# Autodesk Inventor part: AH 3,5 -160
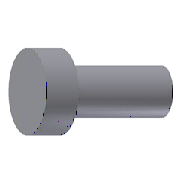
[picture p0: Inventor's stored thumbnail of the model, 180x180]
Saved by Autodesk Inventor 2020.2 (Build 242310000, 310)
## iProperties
Manager: www.cadconsulting.pl
Company: Fabian Stasiak CAD Consulting
Created: 2014-02
Part Number: AH 3,5 -160
Material: DIN 1.2210
Description: Ejector pins-hardened
Document SubType Name: Modeling
Standard: DIN 1530/ISO 6751
Designer: F.Stasiak
Standard Revision: 1
Manufacturer: DME
Language: pl-PL
Size Designation: 3,5 -160
Categories: <MemberInstance><Categories><Category DisplayName="Forma wtryskowa" InternalName="349578f2-f4d4-4954-8c09-8e99297a61c0" Mnemonic="MOLD"><Category DisplayName="K
Mass: 0.191827 g
Surface Area: 2.51725 cm^2
Volume: 0.191827 cm^3
Density: 7.85 g/cm^3
Appearance: Aluminium - ciemne
Catalog Web Link: www.expertbooks.pl
IsCustomPart: 1
Author: F.Stasiak
Subject: Zbiór ćwiczeń. Autodesk Inventor 2020. Kurs Professional
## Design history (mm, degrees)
sketch "Sketch1"
  geometry: L1 (0, 3.5)-(3, 3.5); L2 (0, 0)-(0, 3.5); L3 (3, 1.75)-(160, 1.75); L4 (160, 1.75)-(160, 0); L5 (0, 0)-(160, 0); L6 (3, 3.5)-(3, 1.75); 2 further points
  constraints: 12 end point, 4 point on line, 2 horizontal, 2 perpendicular, 1 coincident
  dimensions: "d6" = 3 distance of L1.start L1.end (derived); "d9" = 160 distance between parallel lines of L4 L2 (derived); "d10" = 7 diameter of L1 L5 (derived); "d13" = 3.5 diameter of L3 L5 (derived)
revolve "Revolution1" sketch "Sketch1" stored, may be unused: angle "d11" = 90 deg
fillet "Fillet1" dims "d29" = 0.3 (derived)
workplane "Work Plane1"
sketch "Sketch2"
  geometry: L1 (3.5, -1.5)-(-3.5, -1.5) reference; L2 (-3.5, -1.5)-(-3.5, 1.5) reference; 4 further points
  constraints: 2 midpoint, 1 horizontal alignment, 1 vertical alignment
hole "Anti_Rotary Hole" sketch "Sketch2" at (0, 0) diameter "d44" = 0.55 (derived); stored, may be unused: countersink angle "d48" = 90 deg, drill point angle "d50" = 118 deg; dims "d45" = 6, "d46" = 4, "d47" = 2, "d49" = 0.825 (derived)
sketch "Sketch3"
  geometry: L1 (-2.05, 2.837)-(-2.05, -2.837); A1 r 3.5 centre (0, 0) between (-2.05, 2.837) and (-2.05, -2.837) reference; 1 further point
  constraints: 2 end point, 2 point on circle, 1 vertical
  dimensions: "d55" = 2.05 distance from line of point (0, 0) L1 (derived)
extrude "Anti_Rotary Plane" cut sketch "Sketch3" distance "d42" = 3.3 (derived); taper "d43" = 0 deg
feature "Rzeźbienie1"
feature "Usuń powierzchnię1"
body "Solid1"
node "Projected Loop1"
feature "Powierzchnia1"
body "Srf1"
other parameters: "d15" = 0, "d24" = 0, "P" = 3.5 [user parameter], "T_" = 3 [user parameter], "H_" = 7 [user parameter], "R" = 0.3 [user parameter], "Anti_Rotary_P" = 2.05 [user parameter], "Anti_Rotary_D" = 0.55 [user parameter], "d51" = 0, "d54" = 0, "d56" = 0, "d57" = 0
